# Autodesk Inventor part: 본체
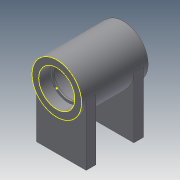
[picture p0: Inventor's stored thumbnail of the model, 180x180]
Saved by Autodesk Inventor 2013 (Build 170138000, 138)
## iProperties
Created: 2020-07
Part Number: 본체
Material: Generic
Document SubType Name: Modeling
Designer: user
Density: 1 g/cm^3
Author: user
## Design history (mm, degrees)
sketch "스케치1"
  geometry: C1 r 26 at (0, 0); 1 further point
  constraints: 1 centre point, 1 coincident
  dimensions: "d0" = 52 diameter of C1
extrude "돌출1" new body sketch "스케치1" stored distance "d2" = 70; taper "d3" = 0 deg
node "작업 평면1"
sketch "스케치2"
  geometry: L1 (-26, 0)-(26, 0); L2 (26, 0)-(26, -64); L3 (26, -64)-(-26, -64); L4 (-26, -64)-(-26, 0); C1 r 26 at (0, 0) reference; 2 further points
  constraints: 8 end point, 2 parallel, 1 coincident, 1 horizontal, 1 midpoint, 1 perpendicular
  dimensions: "d5" = 52 distance of L1.start L1.end; "d7" = 64 distance of L1.end L2.end
extrude "돌출2" join sketch "스케치2" distance "d8" = 10; taper "d9" = 0 deg
sketch "스케치3"
  geometry: L1 (26, -35)-(-26, -35) reference; L2 (-26, -35)-(-26, -30) reference; L3 (-26, -30)-(-64, -30) reference; L4 (-64, -30)-(-64, -20) reference; L5 (-64, -20)-(-26, -20) reference; L6 (-26, -20)-(-26, 20) reference; L7 (-26, 20)-(-64, 20) reference; L8 (-64, 20)-(-64, 30) reference; L9 (-64, 30)-(-26, 30) reference; L10 (-26, 30)-(-26, 35) reference; L11 (-26, 35)-(26, 35) reference; L12 (26, 35)-(26, -35) reference; L13 (0, 35)-(0, -35); L14 (0, 35)-(18.93, 35); L15 (18.93, 35)-(18.93, 23); L16 (18.93, 23)-(16.589, 23); L17 (16.589, 23)-(16.589, 21); L18 (16.589, 21)-(23.144, 21); L19 (23.144, 21)-(23.144, -21); L20 (23.144, -21)-(16.589, -21); L21 (16.589, -21)-(16.589, -23); L22 (16.589, -23)-(19.867, -23); L23 (19.867, -23)-(19.867, -35); L24 (19.867, -35)-(0, -35); 1 further point
  constraints: 24 end point, 7 parallel, 2 midpoint, 2 perpendicular, 2 point on line, 1 collinear
  dimensions: "d10" = 12 distance of L14.end L15.end; "d12" = 42 distance of L18.end L19.end; "d13" = 12 distance of L22.end L23.end; "d14" = 2 distance of L16.end L17.end
revolve "회전1" sketch "스케치3" stored, may be unused: angle "d15" = 90 deg
sketch "스케치4"
  geometry: C1 r 18.93 at (0, 0) reference; C2 r 26 at (0, 0) reference
node "솔리드1"
mirror "대칭1"
node "절단 모서리 투영1"
node "절단 모서리 투영2"
